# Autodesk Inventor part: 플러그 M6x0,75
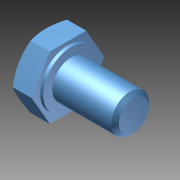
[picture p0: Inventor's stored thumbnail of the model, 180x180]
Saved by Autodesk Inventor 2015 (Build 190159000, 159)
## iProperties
Created: 2026-04
Part Number: 플러그 M6x0,75
Material: 일반
Document SubType Name: Modeling
Designer: User
Density: 1 g/cm^3
Appearance: 기본값
Author: User
Author: jhkim
Description: 6각 머리 볼트 및 6각 머리 나사
Creation Date: 2026-03-26
Sending System: Autodesk Inventor 2026
Preprocessor: ST-DEVELOPER v20.1
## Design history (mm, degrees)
node "플러그 M6x0,751"
body "Solid1"
node "기준1"
